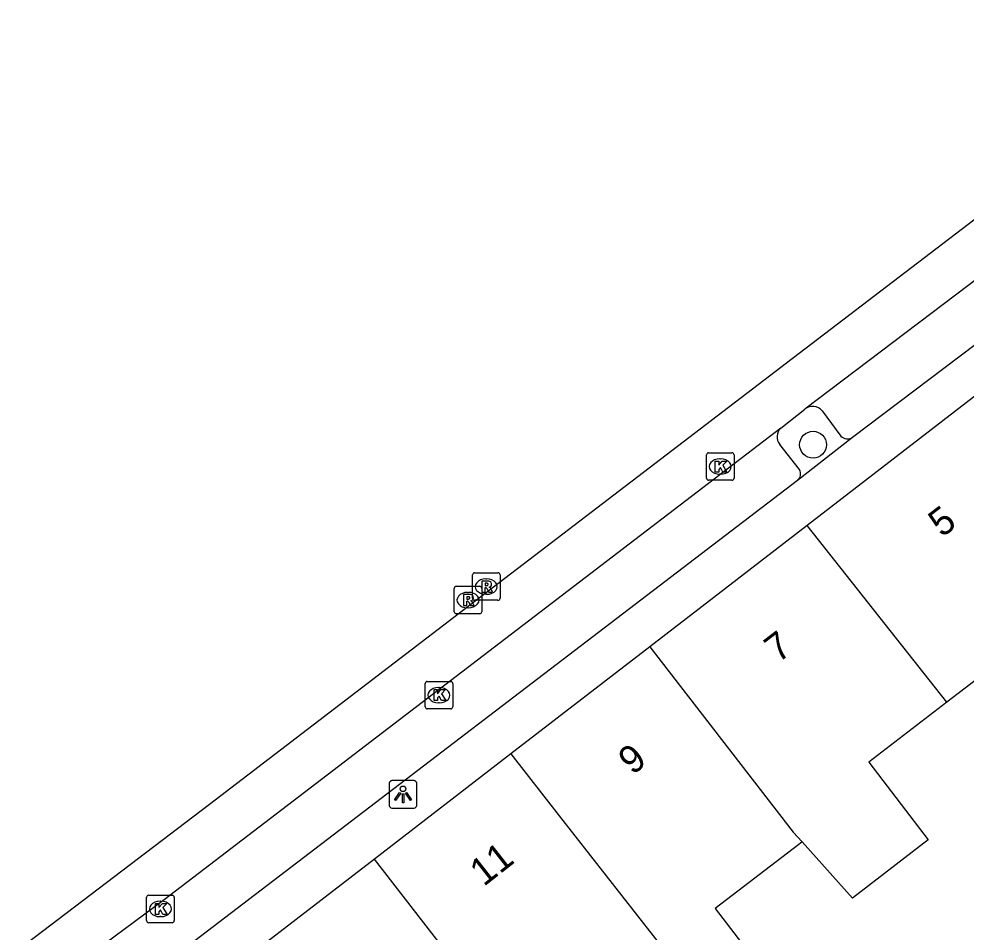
# Model space of a CAD drawing. Extents: x 159503 to 160347, y 382525 to 383272.
# Drawn here: x 159906.33 to 159940.76, y 383230.19 to 383263.4 of the extents above; entities that cross this region are included whole.
import ezdxf

# ---------------------------------------------------------------- set-up
doc = ezdxf.new("R2010")
doc.units = 0
for name, color, linetype in [('IMGEO_Boom', 7, 'Continuous'), ('IMGEO_Kolk', 7, 'Continuous'), ('IMGEO_Lichtpunt', 7, 'Continuous'), ('IMGEO_Pand', 7, 'Continuous'), ('IMGEO_Pand_nummerreeks', 7, 'Continuous'), ('IMGEO_Parkeervlak_open', 7, 'Continuous'), ('IMGEO_Rijbaan_lokaal_gesloten', 7, 'Continuous'), ('IMGEO_Rioolput', 7, 'Continuous'), ('IMGEO_Voetpad_open', 7, 'Continuous')]:
    doc.layers.add(name, color=color, linetype=linetype)

msp = doc.modelspace()

# ---------------------------------------------------------------- linework, layer by layer
at = {"layer": 'IMGEO_Boom'}
msp.add_circle((159935.201, 383247.909), 0.489, dxfattribs=at)
at = {"layer": 'IMGEO_Kolk'}
for p, q in [((159931.325, 383246.692), (159931.325, 383247.544)), ((159931.4, 383247.618), (159932.252, 383247.618)), ((159932.326, 383247.544), (159932.326, 383246.692)), ((159931.813, 383247.398), (159931.838, 383247.398)), ((159931.836, 383246.838), (159931.811, 383246.838)), ((159932.252, 383246.618), (159931.4, 383246.618)), ((159921.173, 383239.302), (159922.025, 383239.302)), ((159921.098, 383238.376), (159921.098, 383239.228)), ((159921.586, 383239.082), (159921.611, 383239.082)), ((159922.099, 383239.228), (159922.099, 383238.376)), ((159922.025, 383238.302), (159921.173, 383238.302)), ((159921.609, 383238.522), (159921.584, 383238.522)), ((159910.971, 383230.6), (159910.971, 383231.452)), ((159911.046, 383231.526), (159911.898, 383231.526)), ((159911.972, 383231.452), (159911.972, 383230.6)), ((159911.459, 383231.306), (159911.484, 383231.306)), ((159911.482, 383230.746), (159911.457, 383230.746)), ((159911.898, 383230.526), (159911.046, 383230.526))]:
    msp.add_line(p, q, dxfattribs=at)
for points in [[(159931.325, 383246.692), (159931.325, 383247.544)], [(159931.4, 383247.618), (159932.252, 383247.618)], [(159932.326, 383247.544), (159932.326, 383246.692)], [(159931.646, 383247.318), (159931.769, 383247.318), (159931.769, 383247.167), (159931.899, 383247.318), (159932.063, 383247.318), (159931.917, 383247.167), (159932.07, 383246.918), (159931.918, 383246.918), (159931.833, 383247.082), (159931.769, 383247.015), (159931.769, 383246.918), (159931.646, 383246.918), (159931.646, 383247.318)], [(159932.252, 383246.618), (159931.4, 383246.618)], [(159921.173, 383239.302), (159922.025, 383239.302)], [(159921.098, 383238.376), (159921.098, 383239.228)], [(159921.419, 383239.002), (159921.542, 383239.002), (159921.542, 383238.851), (159921.672, 383239.002), (159921.836, 383239.002), (159921.69, 383238.851), (159921.843, 383238.602), (159921.691, 383238.602), (159921.606, 383238.766), (159921.542, 383238.699), (159921.542, 383238.602), (159921.419, 383238.602), (159921.419, 383239.002)], [(159922.099, 383239.228), (159922.099, 383238.376)], [(159922.025, 383238.302), (159921.173, 383238.302)], [(159910.971, 383230.6), (159910.971, 383231.452)], [(159911.046, 383231.526), (159911.898, 383231.526)], [(159911.972, 383231.452), (159911.972, 383230.6)], [(159911.292, 383231.226), (159911.415, 383231.226), (159911.415, 383231.075), (159911.545, 383231.226), (159911.709, 383231.226), (159911.563, 383231.075), (159911.716, 383230.826), (159911.564, 383230.826), (159911.479, 383230.99), (159911.415, 383230.923), (159911.415, 383230.826), (159911.292, 383230.826), (159911.292, 383231.226)], [(159911.898, 383230.526), (159911.046, 383230.526)]]:
    msp.add_lwpolyline(points, dxfattribs=at)
for centre, start, end in [((159931.402, 383247.542), 91.552, 178.448), ((159931.402, 383247.542), 91.552, 178.448), ((159932.25, 383247.542), 1.552, 88.448), ((159932.25, 383247.542), 1.552, 88.448), ((159931.402, 383246.694), 181.552, 268.448), ((159931.402, 383246.694), 181.552, 268.448), ((159932.25, 383246.694), 271.552, 358.448), ((159932.25, 383246.694), 271.552, 358.448), ((159921.175, 383239.226), 91.552, 178.448), ((159921.175, 383239.226), 91.552, 178.448), ((159922.023, 383239.226), 1.552, 88.448), ((159922.023, 383239.226), 1.552, 88.448), ((159921.175, 383238.378), 181.552, 268.448), ((159921.175, 383238.378), 181.552, 268.448), ((159922.023, 383238.378), 271.552, 358.448), ((159922.023, 383238.378), 271.552, 358.448), ((159911.048, 383231.45), 91.552, 178.448), ((159911.048, 383231.45), 91.552, 178.448), ((159911.896, 383231.45), 1.552, 88.448), ((159911.896, 383231.45), 1.552, 88.448), ((159911.048, 383230.602), 181.552, 268.448), ((159911.048, 383230.602), 181.552, 268.448), ((159911.896, 383230.602), 271.552, 358.448), ((159911.896, 383230.602), 271.552, 358.448)]:
    msp.add_arc(centre, 0.0765, start, end, dxfattribs=at)
for centre, major_axis, ratio, start_param, end_param in [((159931.812, 383247.118), (-0.387, 0.002), 0.722429, 4.712389, 7.853982), ((159931.837, 383247.118), (-0.39, 0.002), 0.717154, 1.570796, 4.712389), ((159921.585, 383238.802), (-0.387, 0.002), 0.722429, 4.712389, 7.853982), ((159921.61, 383238.802), (-0.39, 0.002), 0.717154, 1.570796, 4.712389), ((159911.458, 383231.026), (-0.387, 0.002), 0.722429, 4.712389, 7.853982), ((159911.483, 383231.026), (-0.39, 0.002), 0.717154, 1.570796, 4.712389)]:
    msp.add_ellipse(centre, major_axis=major_axis, ratio=ratio, start_param=start_param, end_param=end_param, dxfattribs=at)
at = {"layer": 'IMGEO_Lichtpunt'}
for p, q in [((159919.794, 383235.597), (159919.794, 383234.79)), ((159919.794, 383235.597), (159919.794, 383234.79)), ((159920.696, 383235.692), (159919.888, 383235.692)), ((159920.696, 383235.692), (159919.888, 383235.692)), ((159920.79, 383234.79), (159920.79, 383235.597)), ((159920.79, 383234.79), (159920.79, 383235.597)), ((159919.888, 383234.696), (159920.696, 383234.696)), ((159919.888, 383234.696), (159920.696, 383234.696))]:
    msp.add_line(p, q, dxfattribs=at)
for points in [[(159920.168, 383235.261), (159920.207, 383235.233), (159920.019, 383234.971), (159919.981, 383234.998), (159920.168, 383235.261)], [(159920.27, 383235.213), (159920.317, 383235.213), (159920.317, 383234.891), (159920.27, 383234.891), (159920.27, 383235.213)], [(159920.38, 383235.233), (159920.418, 383235.26), (159920.605, 383234.998), (159920.566, 383234.97), (159920.38, 383235.233)]]:
    msp.add_lwpolyline(points, dxfattribs=at)
msp.add_circle((159920.293, 383235.395), 0.0994, dxfattribs=at)
for centre, start, end in [((159919.888, 383235.597), 90, 180), ((159919.888, 383235.597), 90, 180), ((159920.696, 383235.597), 0, 90), ((159920.696, 383235.597), 0, 90), ((159919.888, 383234.79), 180, 270), ((159919.888, 383234.79), 180, 270), ((159920.696, 383234.79), 270, 0), ((159920.696, 383234.79), 270, 360)]:
    msp.add_arc(centre, 0.0946, start, end, dxfattribs=at)
at = {"layer": 'IMGEO_Pand'}
for points in [[(159941.192, 383249.757), (159934.989, 383244.971)], [(159941.192, 383249.757), (159943.034, 383247.333), (159946.121, 383243.176), (159940.069, 383238.544)], [(159934.989, 383244.971), (159931.169, 383242.023), (159929.264, 383240.554)], [(159940.069, 383238.544), (159934.989, 383244.971)], [(159929.264, 383240.554), (159924.217, 383236.662)], [(159929.264, 383240.554), (159934.482, 383233.819), (159934.801, 383233.463)], [(159940.069, 383238.544), (159937.224, 383236.366), (159939.389, 383233.536), (159936.629, 383231.423), (159934.801, 383233.463)], [(159924.217, 383236.662), (159919.25, 383232.832)], [(159924.217, 383236.662), (159925.965, 383234.418), (159934.508, 383223.496)], [(159934.801, 383233.463), (159934.683, 383233.372), (159931.641, 383231.042), (159936.344, 383224.902)], [(159919.25, 383232.832), (159914.452, 383229.133)], [(159925.159, 383226.052), (159924.957, 383226.308), (159924.552, 383225.997), (159919.25, 383232.832)]]:
    msp.add_lwpolyline(points, dxfattribs=at)
at = {"layer": 'IMGEO_Parkeervlak_open'}
for points in [[(159935.537, 383249.146), (159936.212, 383248.227)], [(159934.706, 383247.005), (159933.988, 383247.918)]]:
    msp.add_lwpolyline(points, dxfattribs=at)
for centre, radius, start, end in [((159935.183, 383248.821), 0.48, 42.5755, 126.128), ((159934.324, 383248.195), 0.435, 132.8232, 219.4976), ((159936.454, 383248.452), 0.33, 222.9947, 304.1776), ((159934.437, 383246.849), 0.311, 308.811, 30.1752)]:
    msp.add_arc(centre, radius, start, end, dxfattribs=at)
at = {"layer": 'IMGEO_Rijbaan_lokaal_gesloten'}
for points in [[(159906.328, 383229.559), (159913.257, 383234.839), (159922.547, 383241.953), (159934.232, 383250.883), (159950.623, 383263.397)], [(159949.93, 383260.671), (159948.318, 383259.44), (159940.88, 383253.723), (159934.9, 383249.209)], [(159934.028, 383248.514), (159934.091, 383248.562), (159934.9, 383249.209)], [(159934.028, 383248.514), (159911.61, 383231.36), (159909.455, 383229.758)]]:
    msp.add_lwpolyline(points, dxfattribs=at)
at = {"layer": 'IMGEO_Rioolput'}
for p, q in [((159922.818, 383242.325), (159922.818, 383243.177)), ((159922.893, 383243.251), (159923.745, 383243.251)), ((159923.819, 383243.177), (159923.819, 383242.325)), ((159922.229, 383242.761), (159923.081, 383242.761)), ((159923.306, 383243.031), (159923.331, 383243.031)), ((159922.154, 383241.835), (159922.154, 383242.687)), ((159922.642, 383242.541), (159922.667, 383242.541)), ((159923.155, 383242.687), (159923.155, 383241.835)), ((159923.329, 383242.471), (159923.304, 383242.471)), ((159923.745, 383242.251), (159922.893, 383242.251)), ((159923.081, 383241.761), (159922.229, 383241.761)), ((159922.665, 383241.981), (159922.64, 383241.981))]:
    msp.add_line(p, q, dxfattribs=at)
for points in [[(159922.818, 383242.325), (159922.818, 383243.177)], [(159922.893, 383243.251), (159923.745, 383243.251)], [(159923.819, 383243.177), (159923.819, 383242.325)], [(159922.229, 383242.761), (159923.081, 383242.761)], [(159923.407, 383242.949), (159923.155, 383242.951), (159923.155, 383242.551)], [(159923.155, 383242.551), (159923.279, 383242.551), (159923.279, 383242.713), (159923.29, 383242.713)], [(159923.333, 383242.87), (159923.279, 383242.87), (159923.279, 383242.789)], [(159923.279, 383242.789), (159923.331, 383242.789)], [(159922.154, 383241.835), (159922.154, 383242.687)], [(159922.743, 383242.459), (159922.491, 383242.461), (159922.491, 383242.061)], [(159922.669, 383242.38), (159922.615, 383242.38), (159922.615, 383242.299)], [(159923.155, 383242.687), (159923.155, 383241.835)], [(159923.337, 383242.684), (159923.408, 383242.551), (159923.548, 383242.551), (159923.483, 383242.677)], [(159922.491, 383242.061), (159922.615, 383242.061), (159922.615, 383242.223), (159922.626, 383242.223)], [(159922.615, 383242.299), (159922.667, 383242.299)], [(159922.673, 383242.194), (159922.744, 383242.061), (159922.884, 383242.061), (159922.819, 383242.187)], [(159923.745, 383242.251), (159922.893, 383242.251)], [(159923.081, 383241.761), (159922.229, 383241.761)]]:
    msp.add_lwpolyline(points, dxfattribs=at)
for centre, radius, start, end in [((159922.895, 383243.175), 0.0765, 91.552, 178.448), ((159922.895, 383243.175), 0.0765, 91.552, 178.448), ((159923.743, 383243.175), 0.0765, 1.552, 88.448), ((159923.743, 383243.175), 0.0765, 1.552, 88.448), ((159922.231, 383242.685), 0.0765, 91.552, 178.448), ((159922.231, 383242.685), 0.0765, 91.552, 178.448), ((159923.079, 383242.685), 0.0765, 1.552, 88.448), ((159923.079, 383242.685), 0.0765, 1.552, 88.448), ((159923.289, 383242.66), 0.0533, 26.0293, 88.6989), ((159923.315, 383242.978), 0.19, 274.7715, 282.9687), ((159923.339, 383242.774), 0.0964, 77.0061, 93.1865), ((159923.353, 383242.831), 0.0378, 276.6634, 79.6772), ((159923.406, 383242.839), 0.109, 350.3612, 89.416), ((159923.404, 383242.839), 0.112, 277.5842, 350.9817), ((159923.388, 383242.624), 0.108, 29.5134, 73.7905), ((159922.675, 383242.284), 0.0964, 77.0061, 93.1865), ((159922.689, 383242.341), 0.0378, 276.6634, 79.6772), ((159922.742, 383242.349), 0.109, 350.3612, 89.416), ((159922.625, 383242.17), 0.0533, 26.0293, 88.6989), ((159922.651, 383242.488), 0.19, 274.7715, 282.9687), ((159922.74, 383242.349), 0.112, 277.5842, 350.9817), ((159922.724, 383242.134), 0.108, 29.5134, 73.7905), ((159922.895, 383242.327), 0.0765, 181.552, 268.448), ((159922.895, 383242.327), 0.0765, 181.552, 268.448), ((159923.743, 383242.327), 0.0765, 271.552, 358.448), ((159923.743, 383242.327), 0.0765, 271.552, 358.448), ((159922.231, 383241.837), 0.0765, 181.552, 268.448), ((159922.231, 383241.837), 0.0765, 181.552, 268.448), ((159923.079, 383241.837), 0.0765, 271.552, 358.448), ((159923.079, 383241.837), 0.0765, 271.552, 358.448)]:
    msp.add_arc(centre, radius, start, end, dxfattribs=at)
for centre, major_axis, ratio, start_param, end_param in [((159923.305, 383242.751), (-0.387, 0.002), 0.722429, 4.712389, 7.853982), ((159923.33, 383242.751), (-0.39, 0.002), 0.717154, 1.570796, 4.712389), ((159922.641, 383242.261), (-0.387, 0.002), 0.722429, 4.712389, 7.853982), ((159922.666, 383242.261), (-0.39, 0.002), 0.717154, 1.570796, 4.712389)]:
    msp.add_ellipse(centre, major_axis=major_axis, ratio=ratio, start_param=start_param, end_param=end_param, dxfattribs=at)
at = {"layer": 'IMGEO_Voetpad_open'}
for points in [[(159950.537, 383258.714), (159942.234, 383252.401), (159936.639, 383248.179)], [(159936.639, 383248.179), (159934.632, 383246.606)], [(159934.632, 383246.606), (159911.186, 383228.688)]]:
    msp.add_lwpolyline(points, dxfattribs=at)

# ---------------------------------------------------------------- texts
at = {"layer": 'IMGEO_Pand_nummerreeks'}
for s, rotation, p in [('5', 37.4485, (159939.889, 383244.514)), ('7', 37.4485, (159933.932, 383239.952)), ('9', 39.0356, (159928.64, 383235.87)), ('11', 38.159, (159923.226, 383231.82))]:
    msp.add_text(s, height=1, rotation=rotation, dxfattribs=at).set_placement(p)

doc.saveas('drawing.dxf')
